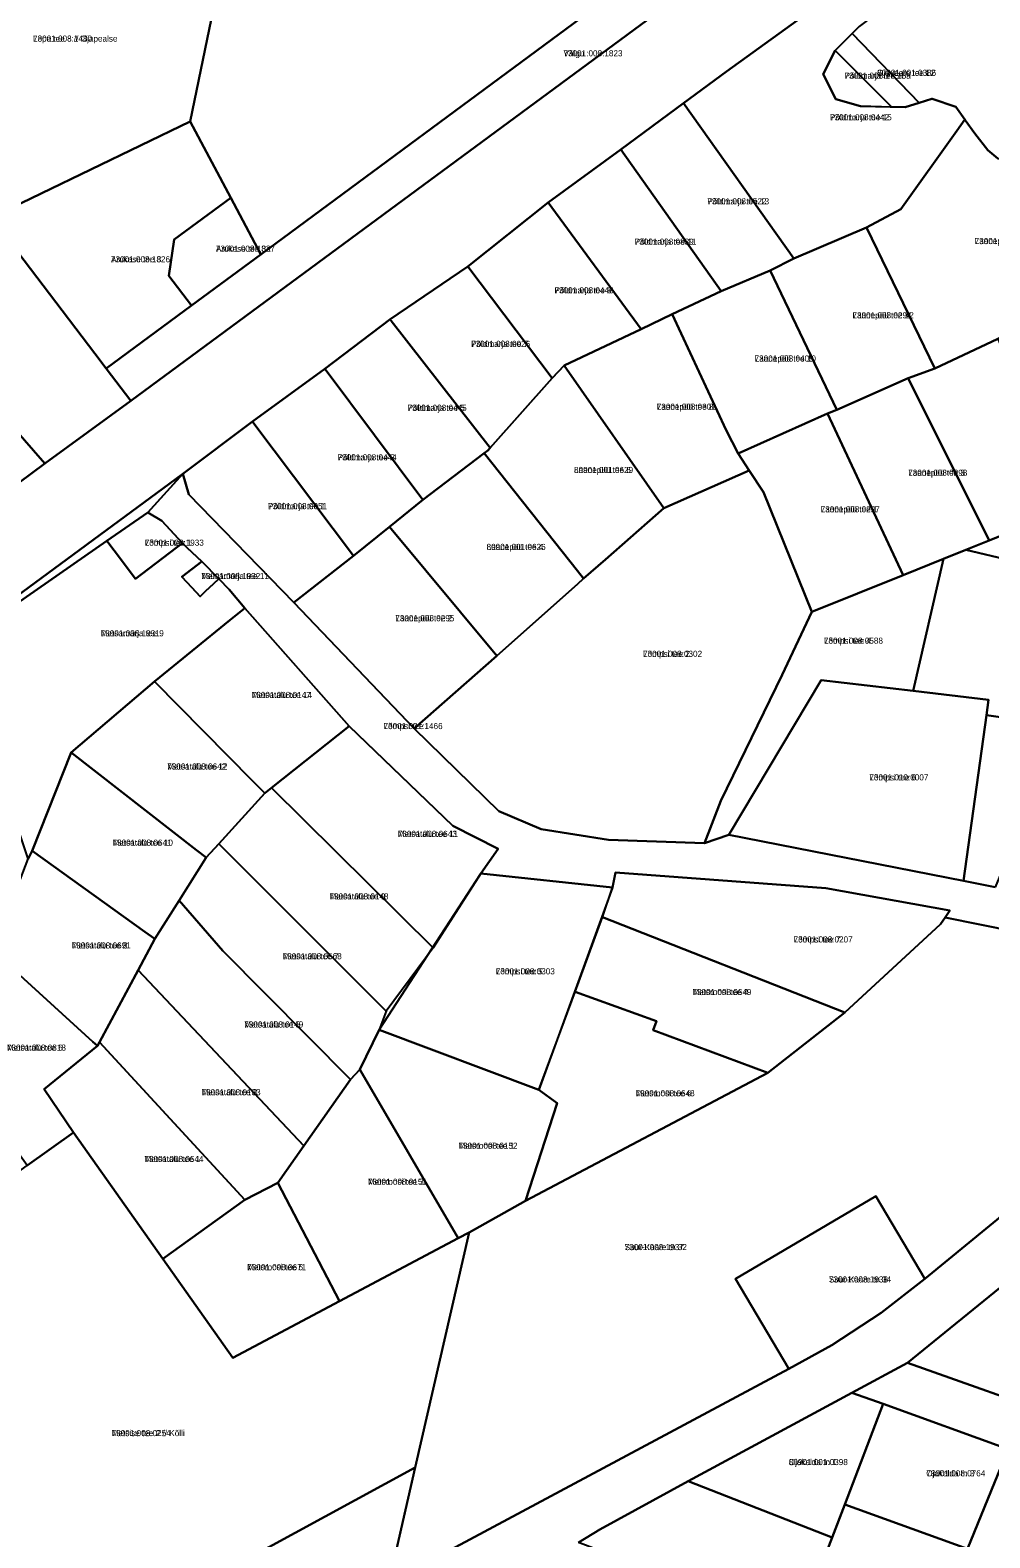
# Model space of a CAD drawing. Extents: x 524000 to 564260, y 6469338 to 6496391.
# Drawn here: x 535246 to 535481.7, y 6471654.6 to 6472024.8 of the extents above; entities that cross this region are included whole.
import ezdxf

# ---------------------------------------------------------------- set-up
doc = ezdxf.new("R2010")
doc.units = 0
for name, color, linetype in [('L_AADRESS', 7, 'Continuous'), ('PIIR', 7, 'Continuous'), ('TUNNUS', 7, 'Continuous')]:
    doc.layers.add(name, color=color, linetype=linetype)

msp = doc.modelspace()

# ---------------------------------------------------------------- linework, layer by layer
at = {"layer": 'PIIR'}
for points in [[(535264.68, 6471941.76), (535285.62, 6471957.21), (535302.63, 6471969.76), (535381.36, 6472027.86), (535412.98, 6472052.43), (535417.85, 6472057.58), (535423.36, 6472063.39), (535428.99, 6472069.36), (535445.91, 6472087.3), (535455.45, 6472094.81), (535465.93, 6472103.05), (535469.22, 6472098.73), (535478.29, 6472086.95), (535298.79, 6471954.5), (535270.76, 6471933.77)], [(535243.25, 6471913.67), (535112.43, 6472063.39), (535118.83, 6472068.12), (535132.04, 6472052.94), (535139.6, 6472044.38), (535173.44, 6472005.7), (535179.55, 6471998.7), (535249.66, 6471918.38)], [(535269.41, 6472067.16), (535271.58, 6472063.44), (535277.89, 6472052.62), (535291.02, 6472030.12), (535285.35, 6472002.41), (535236.46, 6471978.82), (535233.36, 6471976.85), (535204.08, 6472012.54), (535179.55, 6471998.7), (535173.44, 6472005.7), (535205.58, 6472022.79), (535203.5, 6472033.51), (535203.16, 6472035.27), (535229.95, 6472049.72)], [(535406.46, 6472006.89), (535417.01, 6472014.71), (535447.26, 6472036.65), (535452.56, 6472030.34), (535453.57, 6472029.14), (535453.25, 6472028.55), (535449.61, 6472025.76), (535447.83, 6472023.99), (535443.69, 6472019.87), (535440.76, 6472014.03), (535443.82, 6472007.92), (535449.93, 6472006.13), (535460.88, 6472005.88), (535464.3, 6472006.98), (535467.45, 6472008), (535467.5, 6472007.96), (535473.28, 6472005.97), (535475.51, 6472002.85), (535473.53, 6472000.07), (535459.83, 6471980.9), (535451.41, 6471976.33), (535433.57, 6471968.73)], [(535443.69, 6472019.87), (535447.83, 6472023.99), (535464.3, 6472006.98), (535460.88, 6472005.88), (535457.64, 6472005.95)], [(535443.69, 6472019.87), (535457.64, 6472005.95), (535449.93, 6472006.13), (535443.82, 6472007.92), (535440.76, 6472014.03)], [(535249.66, 6471918.38), (535179.55, 6471998.7), (535204.08, 6472012.54), (535233.36, 6471976.85), (535236.46, 6471978.82), (535261.91, 6471945.4), (535264.68, 6471941.76), (535270.76, 6471933.77)], [(535406.46, 6472006.89), (535433.57, 6471968.73), (535427.72, 6471965.78), (535415.66, 6471960.7), (535391.05, 6471995.5)], [(535236.46, 6471978.82), (535285.35, 6472002.41), (535295.28, 6471983.65), (535281.41, 6471973.42), (535280.08, 6471964.53), (535285.62, 6471957.21), (535264.68, 6471941.76), (535261.91, 6471945.4)], [(535451.41, 6471976.33), (535459.83, 6471980.9), (535473.53, 6472000.07), (535475.51, 6472002.85), (535475.63, 6472002.7), (535477.98, 6471999.46), (535481.19, 6471995.34), (535483.66, 6471993.35), (535494.93, 6471990.61), (535504.22, 6471991.78), (535510.35, 6471993.69), (535510.46, 6471993.73), (535506.97, 6471984.28), (535498.81, 6471962.19), (535503.27, 6471958.31), (535483.63, 6471949.06), (535468.16, 6471941.73)], [(535391.05, 6471995.5), (535415.66, 6471960.7), (535403.7, 6471955.12), (535396.04, 6471951.44), (535373.26, 6471982.48)], [(535281.41, 6471973.42), (535295.28, 6471983.65), (535302.63, 6471969.76), (535285.62, 6471957.21), (535280.08, 6471964.53)], [(535373.26, 6471982.48), (535396.04, 6471951.44), (535377.15, 6471942.52), (535374.21, 6471939.41), (535353.5, 6471966.83)], [(535427.72, 6471965.78), (535433.57, 6471968.73), (535451.41, 6471976.33), (535468.16, 6471941.73), (535461.61, 6471939.34), (535444.12, 6471931.59)], [(535374.21, 6471939.41), (535359.01, 6471922.29), (535334.65, 6471953.41), (535334.38, 6471953.75), (535353.5, 6471966.83)], [(535416.94, 6471926.57), (535403.7, 6471955.12), (535415.66, 6471960.7), (535427.72, 6471965.78), (535444.12, 6471931.59), (535441.77, 6471930.73), (535419.87, 6471920.91)], [(535475.74, 6471897.2), (535481.49, 6471899.51), (535501.89, 6471907.74), (535518.07, 6471914.26), (535534.94, 6471921.06), (535541.83, 6471938.63), (535540.8, 6471946.95), (535542.24, 6471957.64), (535543.58, 6471967.51), (535545.47, 6471966.02), (535547.94, 6471965.8), (535548.06, 6471965.81), (535546.44, 6471957.03), (535544.93, 6471948.84), (535545.58, 6471933.49), (535542.46, 6471923.1), (535538.64, 6471923.99), (535532.58, 6471904.27), (535526.64, 6471885.13), (535497.9, 6471891.94)], [(535318.4, 6471941.67), (535334.38, 6471953.75), (535334.65, 6471953.41), (535359.01, 6471922.29), (535358.4, 6471921.62), (535357.52, 6471920.92), (535342.43, 6471909.47), (535318.71, 6471941.27)], [(535396.04, 6471951.44), (535403.7, 6471955.12), (535416.94, 6471926.57), (535419.87, 6471920.91), (535422.61, 6471916.72), (535401.61, 6471907.44), (535377.15, 6471942.52)], [(535461.61, 6471939.34), (535468.16, 6471941.73), (535483.63, 6471949.06), (535501.89, 6471907.74), (535481.49, 6471899.51)], [(535387.26, 6471894.86), (535381.91, 6471890.14), (535380.39, 6471892.06), (535357.52, 6471920.92), (535358.4, 6471921.62), (535359.01, 6471922.29), (535374.21, 6471939.41), (535377.15, 6471942.52), (535401.61, 6471907.44)], [(535300.62, 6471928.69), (535318.4, 6471941.67), (535318.71, 6471941.27), (535342.43, 6471909.47), (535334.29, 6471902.85), (535325.38, 6471895.76), (535300.94, 6471928.26)], [(535444.12, 6471931.59), (535461.61, 6471939.34), (535481.49, 6471899.51), (535475.74, 6471897.2), (535470.27, 6471894.99), (535460.42, 6471891.02), (535441.77, 6471930.73)], [(535325.38, 6471895.76), (535310.78, 6471884.25), (535284.97, 6471910.83), (535283.48, 6471915.85), (535300.62, 6471928.69), (535300.94, 6471928.26)], [(535426.12, 6471911.35), (535422.61, 6471916.72), (535419.87, 6471920.91), (535441.77, 6471930.73), (535460.42, 6471891.02), (535438, 6471881.98)], [(535380.39, 6471888.79), (535360.59, 6471871.19), (535334.29, 6471902.85), (535342.43, 6471909.47), (535357.52, 6471920.92), (535380.39, 6471892.06), (535381.91, 6471890.14)], [(535371.54, 6471828.65), (535361.12, 6471833.08), (535340.33, 6471853.34), (535360.59, 6471871.19), (535380.39, 6471888.79), (535381.91, 6471890.14), (535387.26, 6471894.86), (535401.61, 6471907.44), (535422.61, 6471916.72), (535426.12, 6471911.35), (535438, 6471881.98), (535430.64, 6471866.55), (535415.59, 6471835.58), (535411.58, 6471825.15), (535388.05, 6471826.02)], [(535022.35, 6471718.95), (535020.94, 6471720.57), (535102.87, 6471781.96), (535162.06, 6471826.44), (535283.48, 6471915.85), (535274.91, 6471906.35), (535264.89, 6471899.4), (535230.69, 6471875.66), (535227.92, 6471873.58), (535211.22, 6471861.08), (535198.35, 6471851.45), (535194.21, 6471848.44), (535177.34, 6471836.2), (535162.94, 6471825.75), (535157.14, 6471821.53), (535140.98, 6471809.43), (535102.61, 6471780.33), (535084.1, 6471766.38), (535068.78, 6471754.4), (535052.96, 6471742.26), (535035.38, 6471728.78)], [(535274.91, 6471906.35), (535278.36, 6471904.37), (535283.42, 6471898.88), (535281.88, 6471897.71), (535271.91, 6471890.11), (535266.65, 6471897.06), (535264.89, 6471899.4)], [(535325.38, 6471895.76), (535334.29, 6471902.85), (535360.59, 6471871.19), (535340.33, 6471853.34), (535310.78, 6471884.25)], [(535266.65, 6471897.06), (535271.91, 6471890.11), (535281.88, 6471897.71), (535283.42, 6471898.88), (535284.59, 6471897.72), (535288.2, 6471894.34), (535283.24, 6471890.57), (535285.69, 6471887.93), (535287.73, 6471885.75), (535289.11, 6471887.04), (535291.05, 6471888.84), (535292.37, 6471890.06), (535294.89, 6471887.46), (535298.76, 6471882.91), (535295.07, 6471879.91), (535276.55, 6471864.88), (535256.09, 6471847.45), (535246.48, 6471823.28), (535245.57, 6471821.36), (535233.11, 6471858.23), (535227.92, 6471873.58), (535230.69, 6471875.66), (535264.89, 6471899.4)], [(535417.62, 6471827.27), (535411.58, 6471825.15), (535415.59, 6471835.58), (535430.64, 6471866.55), (535438, 6471881.98), (535460.42, 6471891.02), (535470.27, 6471894.99), (535462.81, 6471862.56), (535440.27, 6471865.23)], [(535481.33, 6471860.37), (535462.81, 6471862.56), (535470.27, 6471894.99), (535475.74, 6471897.2), (535497.9, 6471891.94), (535489.83, 6471860.81), (535516.94, 6471856.63), (535512.6, 6471852.09), (535480.84, 6471856.61)], [(535288.2, 6471894.34), (535292.37, 6471890.06), (535291.05, 6471888.84), (535289.11, 6471887.04), (535287.73, 6471885.75), (535285.69, 6471887.93), (535283.24, 6471890.57)], [(535295.07, 6471879.91), (535298.76, 6471882.91), (535324.32, 6471853.94), (535305.25, 6471838.81), (535303.61, 6471837.46), (535300.65, 6471840.46), (535276.55, 6471864.88)], [(535276.55, 6471864.88), (535300.65, 6471840.46), (535303.61, 6471837.46), (535292.35, 6471825.06), (535289.27, 6471821.66), (535286.9, 6471823.49), (535256.09, 6471847.45)], [(535440.27, 6471865.23), (535462.81, 6471862.56), (535481.33, 6471860.37), (535480.84, 6471856.61), (535475.2, 6471815.95), (535417.62, 6471827.27)], [(535324.32, 6471853.94), (535349.8, 6471829.43), (535360.94, 6471823.77), (535356.69, 6471817.71), (535344.96, 6471799.52), (535305.25, 6471838.81)], [(535482.97, 6471814.41), (535475.2, 6471815.95), (535480.84, 6471856.61), (535512.6, 6471852.09), (535518.8, 6471851.23), (535485.63, 6471820.66)], [(535256.09, 6471847.45), (535286.9, 6471823.49), (535289.27, 6471821.66), (535282.58, 6471811.08), (535276.65, 6471801.69), (535274.19, 6471803.45), (535246.48, 6471823.28)], [(535303.61, 6471837.46), (535305.25, 6471838.81), (535344.96, 6471799.52), (535333.48, 6471783.92), (535292.35, 6471825.06)], [(535282.58, 6471811.08), (535289.27, 6471821.66), (535292.35, 6471825.06), (535333.48, 6471783.92), (535331.71, 6471779.34), (535326.97, 6471769.59), (535324.68, 6471767.19), (535293.36, 6471798.76)], [(535245.57, 6471821.36), (535246.48, 6471823.28), (535274.19, 6471803.45), (535276.65, 6471801.69), (535272.51, 6471793.98), (535263.03, 6471776.28), (535262.55, 6471775.38), (535261.41, 6471776.41), (535236.84, 6471798.77)], [(535389.01, 6471814.34), (535370.93, 6471764.65), (535331.71, 6471779.34), (535356.69, 6471817.71)], [(535389.01, 6471814.34), (535389.79, 6471817.98), (535441.41, 6471814.17), (535471.88, 6471808.68), (535470.71, 6471806.96), (535469.52, 6471805.29), (535446.07, 6471783.63), (535386.55, 6471806.99)], [(535276.65, 6471801.69), (535282.58, 6471811.08), (535293.36, 6471798.76), (535324.68, 6471767.19), (535313.19, 6471750.9), (535272.51, 6471793.98)], [(535547.13, 6471790.52), (535527.35, 6471771.63), (535509.9, 6471756.13), (535486.55, 6471735.35), (535465.7, 6471718.2), (535453.69, 6471738.52), (535419.25, 6471718.18), (535432.3, 6471696.1), (535334.13, 6471643.54), (535340.59, 6471671.9), (535353.8, 6471729.6), (535367.62, 6471737.37), (535427.17, 6471768.76), (535446.07, 6471783.63), (535469.52, 6471805.29), (535470.71, 6471806.96), (535513.7, 6471798.28), (535536.44, 6471794.16)], [(535399.78, 6471781.44), (535379.87, 6471788.66), (535386.55, 6471806.99), (535446.07, 6471783.63), (535427.17, 6471768.76), (535398.99, 6471779.28)], [(535232.71, 6471795.36), (535236.84, 6471798.77), (535261.41, 6471776.41), (535262.55, 6471775.38), (535249.45, 6471764.8), (535256.63, 6471754.15), (535245.26, 6471746), (535236.28, 6471758.46), (535218.08, 6471783.7)], [(535272.51, 6471793.98), (535313.19, 6471750.9), (535306.81, 6471741.8), (535298.7, 6471737.61), (535263.03, 6471776.28)], [(535375.41, 6471761.3), (535370.93, 6471764.65), (535379.87, 6471788.66), (535399.78, 6471781.44), (535398.99, 6471779.28), (535427.17, 6471768.76), (535367.62, 6471737.37)], [(535249.45, 6471764.8), (535262.55, 6471775.38), (535263.03, 6471776.28), (535298.7, 6471737.61), (535278.58, 6471723.1), (535256.63, 6471754.15)], [(535331.71, 6471779.34), (535370.93, 6471764.65), (535375.41, 6471761.3), (535367.62, 6471737.37), (535353.8, 6471729.6), (535351.12, 6471728.21), (535326.97, 6471769.59)], [(535306.81, 6471741.8), (535313.19, 6471750.9), (535324.68, 6471767.19), (535326.97, 6471769.59), (535351.12, 6471728.21), (535322.02, 6471712.75)], [(535259.48, 6471627.78), (535217.58, 6471604.98), (535209.46, 6471626.15), (535192.49, 6471672.19), (535181.92, 6471700.4), (535193.16, 6471708.66), (535222.98, 6471730.03), (535245.26, 6471746), (535256.63, 6471754.15), (535278.58, 6471723.1), (535295.83, 6471698.83), (535322.02, 6471712.75), (535351.12, 6471728.21), (535353.8, 6471729.6), (535340.58, 6471671.89), (535296.36, 6471647.85), (535272.65, 6471634.95)], [(535278.58, 6471723.1), (535298.7, 6471737.61), (535306.81, 6471741.8), (535322.02, 6471712.75), (535295.83, 6471698.83)], [(535465.7, 6471718.2), (535455.01, 6471709.82), (535442.91, 6471701.88), (535432.3, 6471696.1), (535419.25, 6471718.18), (535453.69, 6471738.52)], [(535486.72, 6471718.11), (535510.52, 6471709.11), (535501.62, 6471683.31), (535461.42, 6471697.61)], [(535455.45, 6471687.49), (535446.08, 6471662.8), (535442.96, 6471654.66), (535407.58, 6471668.53), (535447.79, 6471690.25)], [(535455.47, 6471687.48), (535486.15, 6471676.39), (535476.16, 6471651.91), (535446.08, 6471662.8)], [(535486.15, 6471676.39), (535515.72, 6471665.59), (535506.24, 6471641.03), (535476.16, 6471651.91)], [(535296.36, 6471647.85), (535340.58, 6471671.89), (535332.86, 6471638.14), (535327.39, 6471636.17), (535320.95, 6471632.75), (535315.31, 6471628.32), (535310.87, 6471622.87)], [(535380.64, 6471653.45), (535385.87, 6471656.69), (535407.58, 6471668.53), (535442.96, 6471654.66), (535434.86, 6471633.66), (535421.72, 6471638.36), (535395.91, 6471647.63)], [(535434.86, 6471633.66), (535442.96, 6471654.66), (535446.08, 6471662.8), (535476.16, 6471651.91), (535464.96, 6471622.82), (535446.58, 6471629.46)]]:
    msp.add_lwpolyline(points, close=True, dxfattribs=at)
for points in [[(534909.89, 6471661.53), (534983.33, 6471718.25), (535021.91, 6471747.42), (535149.62, 6471843.35), (535148.85, 6471844.29), (535243.25, 6471913.67), (535249.66, 6471918.38), (535270.76, 6471933.77), (535298.79, 6471954.5), (535478.29, 6472086.95)], [(535447.26, 6472036.65), (535417.01, 6472014.71), (535406.46, 6472006.89), (535391.05, 6471995.5), (535373.26, 6471982.48), (535353.5, 6471966.83), (535334.38, 6471953.75), (535318.4, 6471941.67), (535300.62, 6471928.69), (535283.48, 6471915.85), (535162.06, 6471826.44), (535102.87, 6471781.96), (535020.94, 6471720.57), (534983.97, 6471692.22), (534982.09, 6471694.57), (534956.57, 6471674.83), (534949.09, 6471669.07), (534926.45, 6471650.58), (534927.73, 6471648.97), (534909.29, 6471634.83)], [(535381.36, 6472027.86), (535302.63, 6471969.76), (535295.28, 6471983.65), (535285.35, 6472002.41), (535291.02, 6472030.12)], [(535483.66, 6471993.35), (535481.19, 6471995.34), (535477.98, 6471999.46), (535475.63, 6472002.7), (535475.51, 6472002.85), (535473.28, 6472005.97), (535467.5, 6472007.96), (535467.45, 6472008), (535464.3, 6472006.98), (535447.83, 6472023.99), (535449.61, 6472025.76)], [(535513.7, 6471798.28), (535470.71, 6471806.96), (535471.88, 6471808.68), (535441.41, 6471814.17), (535389.79, 6471817.98), (535389.01, 6471814.34), (535356.69, 6471817.71), (535360.94, 6471823.77), (535349.8, 6471829.43), (535324.32, 6471853.94), (535298.76, 6471882.91), (535294.89, 6471887.46), (535292.37, 6471890.06), (535288.2, 6471894.34), (535284.59, 6471897.72), (535283.42, 6471898.88), (535278.36, 6471904.37), (535274.91, 6471906.35), (535283.48, 6471915.85), (535284.97, 6471910.83), (535310.78, 6471884.25), (535340.33, 6471853.34), (535361.12, 6471833.08), (535371.54, 6471828.65), (535388.05, 6471826.02), (535411.58, 6471825.15), (535417.62, 6471827.27), (535475.2, 6471815.95), (535482.97, 6471814.41)], [(535334.13, 6471643.54), (535432.3, 6471696.1), (535442.91, 6471701.88), (535455.01, 6471709.82), (535465.7, 6471718.2), (535486.55, 6471735.35), (535509.9, 6471756.13), (535527.35, 6471771.63), (535547.13, 6471790.52), (535555.36, 6471799.05), (535569.95, 6471795.52), (535567.53, 6471792.92), (535561.63, 6471787.68), (535538.42, 6471767.1), (535517.16, 6471746.52), (535514.57, 6471744.01), (535507.72, 6471736.91), (535486.72, 6471718.11), (535461.42, 6471697.61), (535447.79, 6471690.25), (535407.58, 6471668.53), (535385.87, 6471656.69), (535380.64, 6471653.45)], [(535636.37, 6471622.1), (535605.99, 6471633.1), (535575.78, 6471644.26), (535545.95, 6471654.54), (535515.72, 6471665.59), (535486.15, 6471676.39), (535455.47, 6471687.48), (535447.79, 6471690.25), (535461.42, 6471697.61), (535501.62, 6471683.31), (535528.82, 6471673.51), (535557.22, 6471663.01), (535584.62, 6471652.91), (535612.62, 6471642.71), (535639.99, 6471632.87)]]:
    msp.add_lwpolyline(points, dxfattribs=at)

# ---------------------------------------------------------------- texts
at = {"layer": 'L_AADRESS'}
for s, p in [('Lepa tee 3 // Ojapealse', (535246.73, 6472022.01)), ('Välgu', (535376.98, 6472018.41)), ('Põldmarja tee 15a', (535445.99, 6472012.91)), ('Ojaveere tee L2', (535453.99, 6472013.61)), ('Põldmarja tee 15', (535442.42, 6472002.69)), ('Põldmarja tee 13', (535412.31, 6471982.05)), ('Põldmarja tee 11', (535394.46, 6471972.14)), ('Laanepüü tee 14', (535477.95, 6471972.29)), ('Arukase tee 3', (535265.87, 6471967.82)), ('Arukase tee 3a', (535291.62, 6471970.43)), ('Põldmarja tee 9', (535374.77, 6471960.21)), ('Laanepüü tee 12', (535447.94, 6471954.07)), ('Põldmarja tee 7', (535354.3, 6471947.05)), ('Laanepüü tee 10', (535423.91, 6471943.45)), ('Põldmarja tee 5', (535338.7, 6471931.35)), ('Laanepüü tee 8', (535399.88, 6471931.6)), ('Põldmarja tee 3', (535321.52, 6471919.19)), ('Laanepüü tee 6', (535379.57, 6471916.08)), ('Laanepüü tee 3', (535461.63, 6471915.4)), ('Põldmarja tee 1', (535304.43, 6471907.2)), ('Laanepüü tee 1', (535440.14, 6471906.42)), ('Lõmpsi tee 1', (535274.17, 6471898.23)), ('Laanepüü tee 4', (535358.1, 6471897.19)), ('Metsamarja tee 11', (535288.04, 6471890.04)), ('Laanepüü tee 2', (535335.69, 6471879.68)), ('Metsamarja tee 9', (535263.34, 6471875.98)), ('Lõmpsi tee 2', (535396.52, 6471870.93)), ('Lõmpsi tee 4', (535440.93, 6471874.16)), ('Metsatalu tee 14', (535300.43, 6471860.84)), ('Lõmpsi tee', (535332.8, 6471853.19)), ('Metsatalu tee 12', (535279.67, 6471843.27)), ('Lõmpsi tee 6', (535452.09, 6471840.59)), ('Metsatalu tee 11', (535336.29, 6471826.73)), ('Metsatalu tee 10', (535266.25, 6471824.57)), ('Metsatalu tee 9', (535319.52, 6471811.37)), ('Lõmpsi tee 7', (535433.49, 6471800.8)), ('Metsatalu tee 8', (535256.22, 6471799.33)), ('Metsatalu tee 7', (535308.03, 6471796.67)), ('Lõmpsi tee 5', (535360.36, 6471792.97)), ('Metsroosi tee 4', (535408.64, 6471787.88)), ('Metsatalu tee 5', (535298.59, 6471779.92)), ('Metsatalu tee 6', (535240.31, 6471774.23)), ('Metsatalu tee 3', (535288.11, 6471763.28)), ('Metsroosi tee 6', (535394.69, 6471763.02)), ('Metsroosi tee 1', (535351.19, 6471750.14)), ('Metsatalu tee 1', (535274.08, 6471746.89)), ('Metsroosi tee 3', (535328.96, 6471741.31)), ('Suur-Kaare tn 32', (535392.01, 6471725.25)), ('Metsroosi tee 5', (535299.31, 6471720.32)), ('Suur-Kaare tn 34', (535442.16, 6471717.31)), ('Metsise tee 2 // Kõlli', (535266.03, 6471679.57)), ('Ojakalda tn 1', (535432.3, 6471672.46)), ('Ojakalda tn 3', (535466.06, 6471669.7))]:
    msp.add_text(s, height=1.5, dxfattribs=at).set_placement(p)
at = {"layer": 'TUNNUS'}
for s, p in [('73001:008:1480', (535246.73, 6472022.01)), ('73001:008:1823', (535376.98, 6472018.41)), ('73001:008:1754', (535445.99, 6472012.91)), ('80901:001:0386', (535453.99, 6472013.61)), ('73001:008:0442', (535442.42, 6472002.69)), ('73001:008:0522', (535412.31, 6471982.05)), ('73001:008:0839', (535394.46, 6471972.14)), ('73001:008:0443', (535477.95, 6471972.29)), ('73001:008:1826', (535265.87, 6471967.82)), ('73001:008:1827', (535291.62, 6471970.43)), ('73001:008:0446', (535374.77, 6471960.21)), ('73001:008:0294', (535447.94, 6471954.07)), ('73001:008:0026', (535354.3, 6471947.05)), ('73001:008:0409', (535423.91, 6471943.45)), ('73001:008:0445', (535338.7, 6471931.35)), ('73001:008:0301', (535399.88, 6471931.6)), ('73001:008:0444', (535321.52, 6471919.19)), ('80901:001:0629', (535379.57, 6471916.08)), ('73001:008:0298', (535461.63, 6471915.4)), ('73001:008:0051', (535304.43, 6471907.2)), ('73001:008:0297', (535440.14, 6471906.42)), ('73001:008:1933', (535274.17, 6471898.23)), ('80901:001:0626', (535358.1, 6471897.19)), ('73001:008:1932', (535288.04, 6471890.04)), ('73001:008:0295', (535335.69, 6471879.68)), ('73001:008:1931', (535263.34, 6471875.98)), ('73001:008:0302', (535396.52, 6471870.93)), ('73001:008:0588', (535440.93, 6471874.16)), ('73001:008:0147', (535300.43, 6471860.84)), ('73001:001:1466', (535332.8, 6471853.19)), ('73001:008:0642', (535279.67, 6471843.27)), ('73001:010:0007', (535452.09, 6471840.59)), ('73001:008:0643', (535336.29, 6471826.73)), ('73001:008:0641', (535266.25, 6471824.57)), ('73001:008:0148', (535319.52, 6471811.37)), ('73001:008:0207', (535433.49, 6471800.8)), ('73001:008:0691', (535256.22, 6471799.33)), ('73001:008:0668', (535308.03, 6471796.67)), ('73001:008:0303', (535360.36, 6471792.97)), ('73001:008:0649', (535408.64, 6471787.88)), ('73001:008:0149', (535298.59, 6471779.92)), ('73001:008:0818', (535240.31, 6471774.23)), ('73001:008:0183', (535288.11, 6471763.28)), ('73001:008:0648', (535394.69, 6471763.02)), ('73001:008:0152', (535351.19, 6471750.14)), ('73001:008:0644', (535274.08, 6471746.89)), ('73001:008:0151', (535328.96, 6471741.31)), ('73001:008:1937', (535392.01, 6471725.25)), ('73001:008:0671', (535299.31, 6471720.32)), ('73001:008:1938', (535442.16, 6471717.31)), ('73001:008:0254', (535266.03, 6471679.57)), ('80901:001:0398', (535432.3, 6471672.46)), ('73001:008:0764', (535466.06, 6471669.7))]:
    msp.add_text(s, height=1.5, dxfattribs=at).set_placement(p)

doc.saveas('drawing.dxf')
